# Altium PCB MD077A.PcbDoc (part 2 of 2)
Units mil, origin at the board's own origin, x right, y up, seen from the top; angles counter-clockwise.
Board outline 2838.2 x 1916.85 mil, 4 copper layers (Top Layer, Signal Layer 1, Signal Layer 2, Bottom Layer), stack 61.2 mil thick; 81 components, 30 nets, 187 pads, 201 vias.
Unrouted connection lines stored in the file: 7.
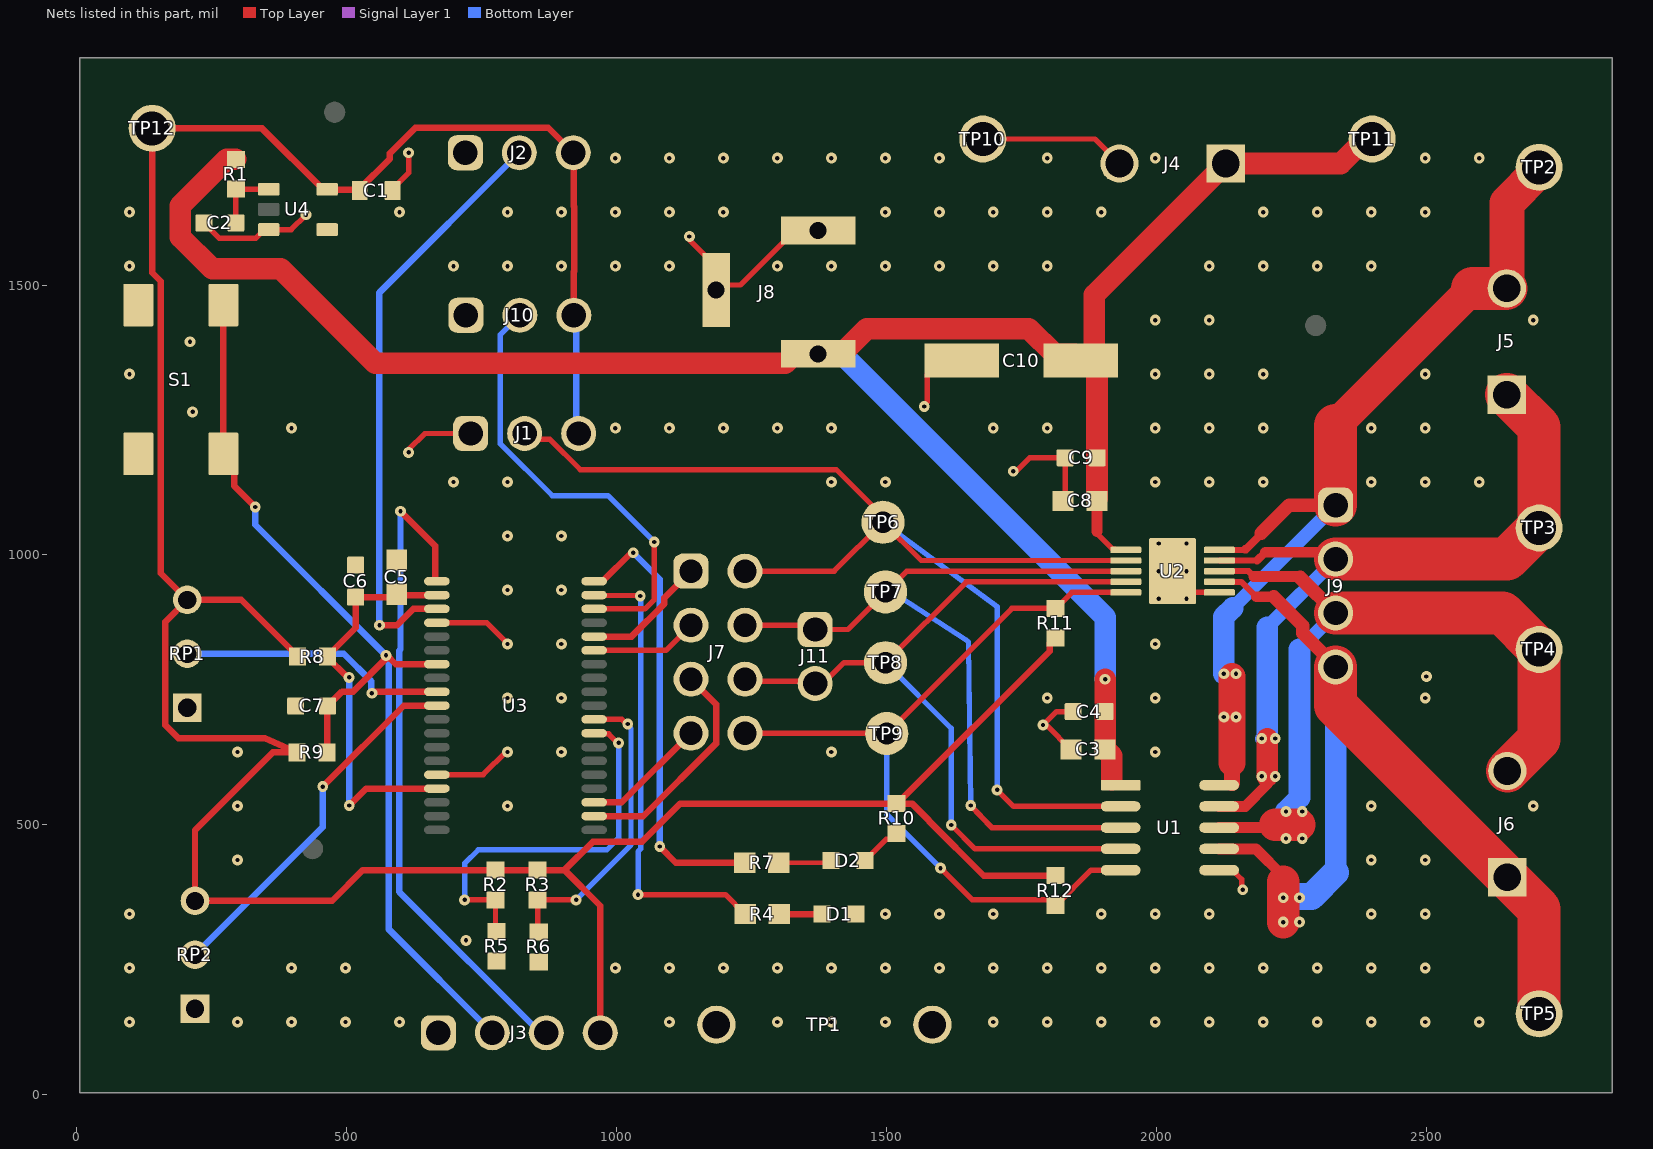
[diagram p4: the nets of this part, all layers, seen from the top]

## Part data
C1: library part CMP-0091702-1, "4.7µF ±10% 25V Ceramic Capacitor X5R 0603 (1608 Metric)", Digikey Part Number=490-14462-1-ND, Manufacturer=Murata, Mouser Part Number=81-GRM188R61E475KE5D, Operating Temperature Range="-55°C to +85°C", TempCo=15%, Temperature Characteristic=X5R, Tolerance_%=10%, ValueDisplayed=4.7uF
C2 C4 C6 C9: library part CMP-0096736-1, "10 µF ±20% 25V Ceramic Capacitor X5R 0603 (1608 Metric)", Manufacturer=Wurth, Operating Temperature Range="-55°C to +85°C", TempCo=15%, Temperature Characteristic=X5R, Tolerance_%=20%, ValueDisplayed=10uF
C3 C5 C8: library part CMP-0006832-5, "CAP, CERM, 0.1 uF, 25 V, +/- 10%, X7R, 0603", Cap_Case=0603, Manufacturer="Wurth Elektronik", Supplier Part Number 1=710-885012206071, TempCo=X7R, Tolerance_%=10%, Value1=Unknown, Value2=25V, ValueDisplayed=0.1uF
C7: library part CMP-0097310-1, "1000 pF ±5% 25V Ceramic Capacitor C0G, NP0 0603 (1608 Metric)", Digikey Part Number=732-7786-1-ND, Manufacturer="Wurth Electronics", Mouser Part Number=710-885012006044, Operating Temperature Range="-55°C to +125°C", TempCo=30ppm/°C, Temperature Characteristic=NP0, Tolerance_%=5%, ValueDisplayed=1nF
C10: library part CMP-0107003-1, "WCAP-ASLI Aluminum Electrolytic Capacitor, V-Chip, D6.3 x H5.5mm, 47uF, 25V", Capacitance Tolerance=+/-20%, Leakage Current=11.75uA, Manufacturer="Wurth Elektronik", Operating Temperature Max=105°C, Operating Temperature Min=-55°C, Rated Voltage (DC)=25V, Ripple Current=220mA
D1: library part CMP-0002894-2, "LED, Green, SMD", Color=green, Manufacturer="Wurth Elektronik", Value1=W, Value2=2V
D2: library part CMP-0002947-3, "LED, Red, SMD", Color=Red, Manufacturer="Wurth Elektronik", Power_TotalModule=72mW, Value1=0.072W, Value2=2V
FID1 FID2 FID3: library part CMP-0077181-1, "Fiducial mark.  There is nothing to buy or mount.", Manufacturer=N/A
H1 H2 H3 H4: library part CMP-0003621-1, "Bumpon, Cylindrical, 0.312 X 0.200, Black", Manufacturer=3M, Supplier Part Number 1=SJ5746-0-ND
J1 J2 J10: library part CMP-0054796-4, "Header, 2.54 mm, 3x1, Gold, TH", Manufacturer="Wurth Elektronik", Supplier Part Number 1=732-5316-ND
J3 J9: library part CMP-0054798-2, "Header, 2.54 mm, 4x1, Gold, TH", Color=Black, Manufacturer="Wurth Elektronik", Supplier Part Number 1=732-5317-ND
J4 J5 J6: library part CMP-0054828-1, "Terminal Block, 5 mm, 2x1, Tin, TH", Manufacturer="Wurth Elektronik", Supplier Part Number 1=732-2026-ND
J7: library part CMP-1502-01078-2, "CONN HEADER VERT 8POS 2.54MM", Color=Black, Contact Resistance=20mΩ, Current Rating=3A, Manufacturer="Wurth Electronics", Max Operating Temperature=105°C, Min Operating Temperature=-40°C, Operating Supply Voltage=250V
J8: library part CMP-0054778-4, "WR-DC DC Power Jack, R/A, TH", Color=Black, Manufacturer="Wurth Elektronik", Supplier Part Number 1=732-5930-ND
J11: library part CMP-0054794-2, "Header, 2.54 mm, 2x1, Gold, TH", Color=Black, Manufacturer="Wurth Elektronik", Supplier Part Number 1=732-5315-ND
LBL1: library part CMP-0003625-1, "Thermal Transfer Printable Labels, 0.650\" W x 0.200\" H - 10,000 per roll", Manufacturer=Brady, Supplier Part Number 1=97C5133
LBL2: library part CMP-00007-1, "Harsh Environment Multi-Purpose Polyester Labels for 3\" Core Printers - 0.375\" x 0.375\", White", Manufacturer=Brady, PartNumber=THT-14-423-10, Supplier Part Number 1=97C5133
Logo1: library part CMP-0074838-1, "Texas Instrument Corporate Signature"
Logo2: library part CMP-0074844-1
Logo3: library part CMP-0074847-1, "FCC_disclaimer"
Logo4: library part CMP-0074769-3, Manufacturer="Texas Instruments"
LOGO5 LOGO6 LOGO7: library part CMP-0074837-2, "IEC 61010-1 Hot Surface Warning", Manufacturer="Texas Instruments"
R1 R8: library part CMP-0025874-4, "RES, 0, 5%, 0.1 W, AEC-Q200 Grade 0, 0603", Manufacturer=Panasonic, Power_W=100mW, Supplier Part Number 1=P0.0GCT-ND, TempCo="600 ppm/C", Tolerance_%=5%, Value2=0.1W, Value_Code=0000, ValueDisplayed=0
R2 R3 R5 R6 R10 R11 R12: library part CMP-0025886-5, "RES, 10 k, 5%, 0.1 W, 0603", Manufacturer=Yageo, Power_W=100mW, Supplier Part Number 1=311-10KGRCT-ND, TempCo="100 ppm/C", Tolerance_%=5%, Value2=0.1W, Value_Code=10k0, ValueDisplayed=10k
R4 R7: library part CMP-0025912-5, "RES, 330, 5%, 0.1 W, 0603", Manufacturer=Yageo, Power_W=100mW, Supplier Part Number 1=311-330GRCT-ND, TempCo="100 ppm/C", Tolerance_%=5%, Value2=0.1W, Value_Code=330R, ValueDisplayed=330
R9: library part CMP-0025814-4, "RES, 47 k, 5%, 0.1 W, AEC-Q200 Grade 0, 0603", Manufacturer=Vishay-Dale, Power_W=100mW, Supplier Part Number 1=541-47KGCT-ND, TempCo="200 ppm/C", Tolerance_%=5%, Value2=0.1W, Value_Code=47k0, ValueDisplayed=47k
RP1 RP2: library part CMP-0001777-2, "Trimming Potentiometer, 50K, 0.5W, TH", Manufacturer=Bourns, Supplier Part Number 1=3352T-503LF-ND
S1: library part CMP-0097347-1, "Tactile Switch SPST-NO Top Actuated Surface Mount", Coil Resistance_ohm=100mΩ, Contact Current Rating=50mA, Digikey Part Number=732-7022-1-ND, Manufacturer="Wurth Electronics", Mouser Part Number=710-430481025816, Operating Force=160gf, Operating Temperature Range="-40°C to +85°C"
SH-J1 SH-J2 SH-J3 SH-J4 SH-J5 SH-J6 SH-J10: library part CMP-0003761-2, "Shunt, 2.54mm, Gold, Black", Manufacturer="Wurth Elektronik", Supplier Part Number 1=732-2678-ND
TP1: library part CMP-0075110-1, "1mm Uninsulated Shorting Plug, 10.16mm spacing, TH", Manufacturer=Harwin, PartNumber=D3082-05, Supplier Part Number 1=952-1873-ND
TP2 TP3 TP4 TP5: library part CMP-0055149-2, "Test Point, Multipurpose, White, TH", Color=White, Manufacturer="Keystone Electronics", Supplier Part Number 1=36-5012-ND
TP6 TP7 TP8 TP9: library part CMP-0055139-2, "Test Point, Miniature, White, TH", Color=White, Manufacturer="Keystone Electronics", Supplier Part Number 1=36-5002-ND
TP10: library part CMP-0055148-2, "Test Point, Multipurpose, Black, TH", Color=Black, Manufacturer="Keystone Electronics", Supplier Part Number 1=36-5011-ND
TP11: library part CMP-0055147-2, "Test Point, Multipurpose, Red, TH", Color=Red, Manufacturer="Keystone Electronics", Supplier Part Number 1=36-5010-ND
TP12: library part CMP-0055150-2, "Test Point, Multipurpose, Orange, TH", Color=Orange, Manufacturer="Keystone Electronics", Supplier Part Number 1=36-5013-ND
U1: library part CMP-0065579-1, "Dual H-Bridge Stepper Driver, SSOP10", Manufacturer="Texas Instruments", Max Supply Voltage=18V, Min Supply Voltage=4V, Nominal Supply Current=3.8mA, Operating Temperature Range="-40°C to +150°C", Switching Frequency=250kHz
U2: library part CMP-0065580-1, "Dual H-Bridge Stepper Driver", Manufacturer="Texas Instruments", Max Supply Voltage=18V, Min Supply Voltage=4V, Nominal Supply Current=3.8mA, Operating Temperature Range="-40°C to +150°C", Switching Frequency=250kHz
U3: library part CMP-0076631-1, "MSP430G2x55 Mixed Signal Microcontroller, DA0038A (TSSOP-38)", Alternate Manufacturer="Texas Instruments", Alternate PartNumber=MSP430G2955IDA38
U4: library part CMP-0077328-2, "40-V Ultralow-Iq Low-Dropout Regulator, DBV0005A (SOT-23-5)", Alternate Manufacturer="Texas Instruments"
ZZ1: library part CMP-0077236-1
ZZ2: library part CMP-0077237-1
ZZ3: library part CMP-0077238-1
ZZ4: library part CMP-0003616-3

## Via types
v1: diameter 20, hole 8, Top Layer to Bottom Layer, tented both sides, 178 vias
v2: diameter 20, hole 8, Top Layer to Bottom Layer, 17 vias
v3: diameter 19.68, hole 7.87, Top Layer to Bottom Layer, tented both sides, 6 vias

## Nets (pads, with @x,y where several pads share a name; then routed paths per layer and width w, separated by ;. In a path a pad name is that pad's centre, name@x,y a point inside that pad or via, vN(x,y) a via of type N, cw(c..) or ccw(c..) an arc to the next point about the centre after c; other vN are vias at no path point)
GND: C1.1 C2.1 C3.2 C4.1 C5.2 C6.1 C7.1 C8.2 C9.1 C10.2 D1.1 J1.1 J2.1 J3.1 J4.2 J8.2 J8.3 J10.1 R5.2 R6.2 RP1.1 RP2.1 S1.3 S1.4 TP1.1 TP1.2 TP10.1 U1.6 U2.6 U2.11 U3.4 U3.15 U4.3 U4.4 | length 1911.6
  Top Layer w10: C2.1@235.94,1615 264.57,1586.38 331.77,1586.38 345.39,1600 U4.3@355,1600 ; U4.3@355.87,1602.6 397.6,1602.6 v1(425,1630) ; C1.1@585.51,1675 585.51,1677.95 615,1707.44 v1(615,1745) ; v1@615,1195 645,1225 J1.1@730,1225 ; U3.15@667.33,593.05 753.05,593.05 v1@797,637 ; U3.4@667.33,874.54 759.46,874.54 v1@797,837 ; v1(1135,1590) 1136.91,1588.09 1136.91,1581.85 1185,1533.76 J8.3@1185,1505 ; J8.3@1190,1500 1229.37,1500 1330.36,1601 J8.2@1373.67,1601 ; v1(1570,1275) 1570,1277.71 1575.87,1283.57 1575.87,1333.5 1602.36,1360 C10.2@1639.76,1360 ; TP10.1@1678.42,1770.38 1886.19,1770.38 1930,1726.57 J4.2@1930,1725 ; v1@1740,1155 1765,1180 C9.1@1830.94,1180 1830.94,1100.94 C8.2@1830,1100 ; C3.2@1842.01,640 1841.02,640 1797.94,683.09 1791.91,683.09 v1(1790,685) 1815,710 C4.1@1845.94,710 ; v3(2055.59,918.82) 2067.4,930.63 U2.6@2116.61,930.63 ; U1.6@2116.18,416.26 2141.04,416.26 2158.09,399.21 2158.09,381.91 v1(2160,380)
  other v1: 98,135 298,135 398,135 498,135 598,135 1098,135 1298,135 1398,135 1498,135 1698,135 1798,135 1898,135 1998,135 2098,135 2198,135 2298,135 2398,135 2498,135 2598,135 98,235 398,235 498,235 998,235 1098,235 1198,235 1298,235 1398,235 1498,235 1598,235 1698,235 1798,235 1898,235 1998,235 2098,235 2198,235 2298,235 2398,235 2498,235 721.27,286.26 98,335 1498,335 1598,335 1698,335 1898,335 1998,335 2098,335 2398,335 2498,335 298,435 2398,435 2498,435 298,535 798,535 2398,535 2698,535 298,635 798,635 898,635 1398,635 1998,635 798,735 898,735 1798,735 1998,735 2498,735 2500,775 798,835 898,835 1998,835 798,935 898,935 798,1035 898,1035 698,1135 798,1135 1398,1135 1498,1135 1998,1135 2098,1135 2198,1135 2398,1135 2498,1135 2598,1135 1735,1155 615,1190 398,1235 998,1235 1098,1235 1198,1235 1298,1235 1398,1235 1698,1235 1798,1235 1998,1235 2098,1235 2198,1235 2398,1235 2498,1235 215,1265 98,1335 1998,1335 2098,1335 2198,1335 2498,1335 210,1395 1998,1435 2098,1435 2698,1435 98,1535 698,1535 798,1535 898,1535 998,1535 1098,1535 1298,1535 1398,1535 1498,1535 1598,1535 1698,1535 1798,1535 2098,1535 2198,1535 2298,1535 2398,1535 98,1635 598,1635 798,1635 898,1635 998,1635 1098,1635 1198,1635 1498,1635 1598,1635 1698,1635 1798,1635 1898,1635 2198,1635 2298,1635 2398,1635 2498,1635 998,1735 1098,1735 1198,1735 1298,1735 1398,1735 1498,1735 1598,1735 1798,1735 1998,1735 2498,1735 2598,1735
  other v3: 2004.41,918.82 2004.41,970 2055.59,970 2004.41,1021.18 2055.59,1021.18
ID1: R2.2 R5.1 U3.27 | length 717.4
  Top Layer w10: v2(718.73,361.27) R2.2@776,361.27 776,304.99 R5.1@778,302.99 ; U3.27@958.67,669.82 959.77,668.72 985.36,668.72 1002.08,652 v2(1004,652)
  Bottom Layer w10: v2(718.73,361.27) 718.73,428.73 744,454 982,454 1004,476 v2(1004,652)
ID2: R3.2 R6.1 U3.28 | length 567.9
  Top Layer w10: R6.1@856,301.56 854,303.56 R3.2@854,361.27 v2(925.27,361.27) ; U3.28@958.67,695.41 1009.88,695.41 1018.29,687 v2(1021,687)
  Bottom Layer w10: v2(925.27,361.27) 1026.87,462.87 1026.87,678.42 1021,684.29 v2(1021,687)
IN1/EN: J1.2 J7.2 TP6.1 U1.2 U2.2 | length 2355.6
  Top Layer w10: J1.2@830,1225 840.52,1214.48 876.38,1214.48 932.99,1157.87 1407.47,1157.87 1493.61,1071.74 TP6.1@1493.61,1060.52 ; J7.2@1238,970 1403.09,970 TP6.1@1493.61,1060.52 ; v1(1705,565) 1735.63,534.37 1934.37,534.37 U1.2@1935,535 ; U2.2@1943.39,989.68 1564.44,989.68 TP6.1@1493.61,1060.52
  Bottom Layer w10: TP6.1@1493.61,1060.52 1705,904.13 v1(1705,565)
IN1/EN_MCU: J7.1 U3.34 | length 235.9
  Top Layer w12: U3.34@958.67,848.95 1027.99,848.95 1088.87,909.83 1088.87,920.87 J7.1@1138,970
IN2/IN1: J7.4 J11.1 TP7.1 U1.3 U2.3 | length 1532
  Top Layer w10: J7.4@1238,870 1360,870 J11.1@1368,862 1428.6,862 TP7.1@1498.29,931.69 1499.46,931.69 1537.77,970 U2.3@1943.39,970 ; v1(1656,536) 1695,495 U1.3@1933.82,495
  Bottom Layer w10: TP7.1@1498.29,931.69 1504.61,933.03 1508.62,933.03 1648.3,842.06 1651.91,838.45 1651.97,834.39 v1@1656,539 ; v1@1655,535 v1(1656,536)
IN2/IN1_MCU: J7.3 U3.33 | length 198.6
  Top Layer w10: U3.33@958.67,823.36 1091.36,823.36 J7.3@1138,870
IN3/IN2: J7.6 J11.2 TP8.1 U1.4 U2.4 | length 1465.4
  Top Layer w10: J7.6@1238,770 1242,766 1364,766 J11.2@1368,762 1382.87,762 1421.4,800.53 TP8.1@1498.29,800.53 1648.08,950.32 U2.4@1943.39,950.32 ; v1(1620,500) 1664.37,455.63 U1.4@1929.37,455.63
  Bottom Layer w10: TP8.1@1498.29,800.53 1620,678.82 v1(1620,500)
IN3/IN2_MCU: J7.5 U3.21 | length 419.8
  Top Layer w12: U3.21@958.67,516.28 1049.83,516.28 1184.35,650.8 1184.35,723.65 J7.5@1138,770
IN4/nFAULT: J7.8 R11.2 R12.2 TP9.1 U1.5 U2.5 | length 1501.9
  Top Layer w10: J7.8@1238,670 1238.32,669.68 1500.32,669.68 TP9.1@1500.64,669.36 1732.4,901.12 R11.2@1813,901.12 1813.98,901.12 1843.5,930.63 U2.5@1943.39,930.63 ; v1@1606.45,416.26 1602.71,420 v1(1600,420) 1658.37,361.63 1802.03,361.63 R12.2@1812.78,350.88 1813.77,350.88 1879.14,416.26 U1.5@1933.82,416.26
  Bottom Layer w10: TP9.1@1500.64,669.36 1500.64,519.36 v1(1600,420)
IN4/nFAULT_MCU: J7.7 U3.22 | length 234.8
  Top Layer w12: U3.22@958.67,541.87 1009.87,541.87 J7.7@1138,670
  Signal Layer 1 w12: J7.7@1149.36,680.06 J7.7@1151.06,681.76
"MCU 3V3": C1.2 J1.3 J2.3 J3.4 J10.3 R2.1 R3.1 R8.2 R9.1 R10.1 R11.1 R12.1 RP1.3 RP2.3 TP12.1 U4.5 | length 5942.5
  Top Layer w12: R8.2@409.44,811.65 409.44,812.63 305.07,917.01 RP1.3@205.01,917.01 ; J10.3@921,1444 921,1524.24 921.87,1525.11 921.87,1644.89 921,1645.76 921,1744 J2.3@920,1745 873.65,1791.35 627.59,1791.35 580.42,1744.18 580.42,1733.89 523.29,1676.75 523.29,1676.2 465.33,1676.2 U4.5@464.13,1677.4 456.26,1677.4 343.66,1790 TP12.1@140,1790 140,1522.78 156,1506.78 156,966.02 RP1.3@205.01,917.01 ; J3.4@970,115 970,350.29 903.91,416.38 ; R12.1@1812.78,406 1680.24,406 1578.78,507.46 1578.78,508.22 1547.44,539.56 R10.1@1519.98,539.56 ; R11.1@1813,846 1812.02,846 1802.27,836.25 1802.27,821.84 R10.1@1519.98,539.56 ; RP1.3@205.01,917.01 164.56,876.56 164.56,684.68 188.37,660.87 348.02,660.87 R9.1@408.44,634.2 363.44,634.2 219.38,490.14 RP2.3@219.38,359.54 473.4,359.54 530.25,416.38 R2.1@776,416.38 R3.1@854,416.38 903.91,416.38 ; 903.91,416.38 956.46,468.94 1047.34,468.94 1117.96,539.56 R10.1@1519,539.56 R10.1@1519.98,539.56
  Bottom Layer w12: J10.3@921,1444 925.5,1439.5 925.5,1229.5 J1.3@930,1225
MCU_STATUS: R4.1 U3.37 | length 854.9
  Top Layer w10: U3.37@958.81,925.86 U3.37@958.67,925.72 959.53,924.86 1043.14,924.86 v2(1044,924) ; v2(1040,371) 1201.52,371 1237.52,335 R4.1@1238.5,335
  Bottom Layer w10: v2(1040,371) 1040,450.72 1044.75,455.47 1044.75,923.25 v2(1044,924)
MODE_SELECT: J2.2 U3.3 | length 1101.1
  Top Layer w12: v2(561,870) 593.5,870 623.64,900.13 U3.3@667.33,900.13
  Bottom Layer w12: v2(561,870) 561,1486 J2.2@820,1745
NetC2_2: C2.2 R1.1 U4.1 | length 120.1
  Top Layer w10: C2.2@295,1615 R1.1@295,1677.44 306.69,1677.44 306.73,1677.4 U4.1@352.6,1677.4
NetC5_1: C5.1 C6.2 R8.1 U3.2 U3.16 | length 756.4
  Top Layer w12: v2(505,536) 536.46,567.46 U3.16@667.33,567.46 ; v2@507,775 500.22,775 464.56,810.66 R8.1@464.56,811.65 464.56,812.63 517,865.07 C6.2@517,922 587.5,922 C5.1@593,927.5 594.78,925.72 U3.2@667.33,925.72
  Bottom Layer w12: v2(504.84,773.36) 504.92,773.28 504.92,536.08 v2(505,536)
NetD1_2: D1.2 R4.2 | length 79.5
  Top Layer w12: R4.2@1301.5,335 D1.2@1381.01,335
NetD2_1: D2.1 R7.2 | length 99.7
  Top Layer w8: R7.2@1300.5,430 1393.01,430 D2.1@1397.01,434 D2.1@1398.5,434
NetD2_2: D2.2 R10.2 | length 79.9
  Top Layer w10: D2.2@1460,434 1499.69,473.69 1508.25,473.69 R10.2@1519,484.44
nFAULT_STATUS: R7.1 U3.38 | length 828.4
  Top Layer w12: U3.38@958.67,951.32 959.89,952.54 975.64,952.54 1025.57,1002.47 1029.47,1002.47 v2(1031,1004) ; v2(1080,460) 1110,430 R7.1@1237.5,430
  Bottom Layer w12: v2(1031,1004) 1080,955 v2(1080,460)
OUT1: J5.2 J9.1 TP2.1 U1.10 U2.10 | length 1687.5
  Top Layer w10: U1.10@2116.18,573.74 2135.78,573.74 U1.10@2140,577.96
  Top Layer w11: U2.10@2116.61,1009.37 2163.06,1009.37 2164.37,1010.68
  Top Layer w15: 2164.37,1010.68 2165.68,1010.68 2195,1040
  Top Layer w25: 2194.34,1040.66 2246.19,1092.5 J9.1@2331.9,1092.5
  Top Layer w30: U1.10@2140,577.96 2140,615
  Top Layer w50: 2140,615 v1@2140,775
  Top Layer w60: 2331.9,1239.93 2585.79,1493.81
  Top Layer w65: J5.2@2649.02,1493.81 2649.02,1652.23 2708.69,1711.9 TP2.1@2708.69,1717.85
  Top Layer w80: J9.1@2331.9,1092.5 2331.9,1239.93 ; 2585.79,1493.81 J5.2@2647.11,1493.81
  Bottom Layer w25: 2141.18,901.79 J9.1@2331.9,1092.5
  Bottom Layer w40: v1(2125,780) 2125,885.6 2141.18,901.79
  other v1: 2125,700 2147.5,700 2147.5,780
OUT2: J5.1 J9.2 TP3.1 U1.9 U2.9 | length 1442.2
  Top Layer w11: U2.9@2116.61,989.68 2186.62,989.68
  Top Layer w15: 2186.62,989.68 2201.93,1005
  Top Layer w20: U1.9@2116.18,534.37 2164.37,534.37 2205.25,575.25 ; 2201.93,1005 J9.2@2315,1005
  Top Layer w40: 2205,590 2205,660
  Top Layer w80: J9.2@2331.9,992.5 2649.3,992.5 2706.8,1050 TP3.1@2708.69,1050 2708.69,1237.29 J5.1@2649.02,1296.96
  Bottom Layer w25: v1(2195,660) 2205,670 ; 2205,865.6 J9.2@2331.9,992.5
  Bottom Layer w40: 2205,670 2205,865.6
  other v1: 2195,590 2220,590 2220,660
OUT3: J6.2 J9.3 TP4.1 U1.8 U2.8 | length 1460.6
  Top Layer w10: 2170,970 2170.71,970
  Top Layer w11: U2.8@2116.61,970 2170,970
  Top Layer w12: 2170.71,970 2180.35,960.35
  Top Layer w20: U1.8@2116.18,495 2215,495 ; 2180.35,960.35 2264.65,960.35 2265,960
  Top Layer w25: 2266.07,958.33 J9.3@2331.9,892.5 ; TP4.1@2708.69,810.26 TP4.1@2708.69,824.98
  Top Layer w60: 2220,500 2265,500
  Top Layer w80: J9.3@2331.9,892.5 2641.17,892.5 TP4.1@2708.69,824.98 ; J6.2@2650,600 2708.69,658.69 TP4.1@2708.69,821.75
  Bottom Layer w25: 2265,825.6 J9.3@2331.9,892.5
  Bottom Layer w40: v1(2240,525) 2265,550 2265,825.6
  other v1: 2240,475 2270,475 2270,525
OUT4: J6.1 J9.4 TP5.1 U1.7 U2.7 | length 1796.5
  Top Layer w11: U2.7@2116.61,950.32 2157.34,950.32 2185.15,922.5
  Top Layer w20: U1.7@2116.18,455.63 2184.37,455.63 2235,405 ; 2185.15,922.5 2217.5,922.5
  Top Layer w25: 2217.5,922.5 2270.88,869.12 2270.88,854.95 2331.9,793.93 J9.4@2331.9,792.5
  Top Layer w60: v1(2235,320) v1(2235,365) 2235,395
  Top Layer w80: J9.4@2331.9,792.5 2331.9,721.25 2708.69,344.46 TP5.1@2708.69,150
  Bottom Layer w40: 2331.9,411.9 J9.4@2331.9,792.5
  Bottom Layer w50: v1@2237.5,367.5 2287.5,367.5 2331.9,411.9
  other v1: 2265,320 2265,365
RST/SBWTDIO: C7.2 J3.2 R9.2 S1.1 S1.2 U3.7 | length 1895.4
  Top Layer w12: S1.2@272.05,1177.95 S1.2@275,1175 ; S1.1@272.05,1462.8 S1.2@272.05,1187.2 291.68,1167.57 291.68,1128.32 v2(331,1089) ; R9.2@463.56,634.2 464.28,634.92 C7.2@464.28,719.6 ; C7.2@465,720.32 491.72,747.03 512.27,747.03 571.47,806.23 571.47,812.47 v2(573,814) 575.16,814 591.39,797.77 U3.7@667.33,797.77
  Bottom Layer w12: v2(331,1089) 331,1056 v2(573,814) 577.88,809.12 577.88,307.12 J3.2@770,115
SBWTCK: J3.3 U3.1 | length 1244.6
  Top Layer w12: v2(600,1081) 664.31,1016.69 664.31,953.05 665.6,953.05 U3.1@667.33,951.32
  Bottom Layer w12: v2(600,1081) 600,825.25 597.76,823.01 597.76,376.01 858.77,115 J3.3@870,115
"SPD_REF 1": RP1.2 U3.9 | length 505.9
  Top Layer w12: v2(547,744) 549.16,744 551.76,746.59 U3.9@667.33,746.59
  Bottom Layer w12: RP1.2@205.01,817.01 494.95,817.01 545.47,766.49 545.47,745.53 v2(547,744)
"SPD_REF 2": RP2.2 U3.10 | length 682.9
  Top Layer w12: v2(456,571) 606,721 U3.10@667.33,721
  Bottom Layer w12: RP2.2@219.38,259.54 456,496.16 v2(456,571)
STEP_SELECT: J10.2 U3.36 | length 838.6
  Top Layer w10: U3.36@958.67,900.13 1052.48,900.13 1070,917.65 v2(1070,1024)
  Bottom Layer w10: J10.2@821,1444 784.65,1407.65 784.65,1206.21 881.02,1109.84 984.16,1109.84 v2(1070,1024)
VM: C3.1 C4.2 C8.1 C9.2 C10.1 J4.1 J8.1 R1.2 TP11.1 U1.1 U2.1 | length 4141.2
  Top Layer w6: U2.1@1923.94,1009.37 U2.1@1943.39,1009.37
  Top Layer w10: 1890,1043.31 1890,1040.12 1919.84,1010.28 1923.03,1010.28 U2.1@1923.94,1009.37
  Top Layer w20: 1890,1043.31 C8.1@1890,1100
  Top Layer w40: R1.2@295,1732.56 278.22,1732.56 192.32,1646.66 192.32,1588.91 251.19,1530.04 377.85,1530.04 552.89,1355 1312.71,1355 1330.36,1372.65 J8.1@1373.67,1372.65 ; J8.1@1380,1375 1383.24,1378.24 1422.57,1378.24 1463.7,1419.37 1763.46,1419.37 1811.34,1371.5 1848.74,1371.5 C10.1@1860.24,1360 ; C10.1@1885,1373.79 1885,1481.57 J4.1@2128.43,1725 ; C8.1@1890,1105 C10.1@1890,1336 ; v1(1905,770) C4.2@1905,710 C3.1@1905,640 1916.93,628.07 1916.93,584.18 ; J4.1@2130,1725 2341.59,1725 2386.97,1770.38 TP11.1@2399.69,1770.38
  Bottom Layer w15: J8.1@1373.67,1372.65 J8.1@1416.98,1372.65
  Bottom Layer w40: J8.1@1416.98,1372.65 1905,884.63 v1(1905,770)
pads on no net: FID1.1 FID2.1 FID3.1 H1.0 H2.0 H3.0 H4.0 LBL1.0 LBL2.0 SH-J1.0 SH-J2.0 SH-J3.0 SH-J4.0 SH-J5.0 SH-J6.0 SH-J10.0 U3.5 U3.6 U3.8 U3.11 U3.12 U3.13 U3.14 U3.17 U3.18 U3.19 U3.20 U3.23 U3.24 U3.25 U3.26 U3.29 U3.30 U3.31 U3.32 U3.35 U4.2

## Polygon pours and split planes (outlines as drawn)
GND on Signal Layer 1 "SIGNAL_LAYER_1_GND_P184" (solid, pour order 184): 28.76,3239.13 4589.98,3239.13 4589.98,2.13 20.98,2.13
GND on Signal Layer 2 "SIGNAL_LAYER_2_GND_P275" (solid, pour order 275): 20.98,2.13 4589.98,2.13 4589.98,3241.13 20.98,3241.13
GND on Bottom Layer "BOTTOM_LAYER_GND_P277" (solid, remove dead copper, pour order 277): 4589.33,3329.38 34.92,3329.38 34.92,106.47 4589.33,106.47
GND on Top Layer "TOP_LAYER_GND_P278" (solid, remove dead copper, pour order 278): -689.89,-781.89 5340.11,-781.89 5340.11,3389.11 -689.89,3389.11

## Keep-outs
Keep-Out Layer:
  text ".Layer_Name" at 575,-2292.49 h25

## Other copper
Top Layer:
  rectangle net OUT4: 2215,300 2285,385
  rectangle net OUT3: 2225,459.54 2285.03,550
  rectangle net OUT2: 2180,575 2235,680
  rectangle net OUT1: 2105,685 2165,795
  text ".Layer_Name" at 575,-2292.49 h25
Bottom Layer:
  text ".Layer_Name" at 575,-2292.49 h25

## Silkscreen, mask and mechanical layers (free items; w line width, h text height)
Top Overlay:
  circle w15: c659.71,1002.62 r7.07
  lines w10: 649.28,1512.1 1105,1512.1 ; 645,1285 1105,1285 ; 645,1285 645,1110 1105,1110 1105,1285 ; 645,1285 1105,1285 ; 645,1285 645,1875 1105,1875 1105,1285 ; 425,40 1110,40 1110,180 425,180 425,40 ; 1773,317 2219,317 2219,764 1773,764 1773,317 ; 1786,827 2212,827 2212,1214 1786,1214 1786,827
  text "VM" at 1118,1848 h40
  text "OUT1" at 2648,1813 h40
  text "Mode Select" at 655,1811.02 h85
  text "4-18V / 4A" at 2470,1785 h35
  text "3.3 V" at 65,1675 h30
  text "Stepper" at 899.56,1670.25 h35 r315
  text "BDC" at 692.31,1660 h40 r315
  text "GND" at 1628,1643 h40
  text "VM" at 2368,1643 h40
  text "(DRV8421A / ONLY)" at 353.73,1316 h55
  text "Half / Step" at 664.52,1283 h30
  text "Full / Step" at 886,1283 h30
  text "OUT2" at 2648,1138 h40
  text "Enable" at 881,1131 h30
  text "Sleep" at 661,1126 h30
  text "(DRV8421B / ONLY)" at 354.85,1120 h55
  text "Reset" at 131,1100 h30
  text "OUT1" at 2388,1073 h40
  text "IN1/EN" at 1561,1045 h33
  text "OUT2" at 2388,968 h40
  text "MCU Ctrl 1" at 324,948 h35 r270
  text "IN2/IN1" at 1566,913 h33
  text "OUT3" at 2648,913 h40
  text "OUT3" at 2383,868 h40
  text "DRV8421 DGQ" at 1850,843 h33
  text "IN3/IN2" at 1566,786 h33
  text "OUT4" at 2388,778 h40
  text "IN4/" at 1578,682 h33
  text "nFAULT" at 1573,624 h33
  text "MD077A" at 1086.75,553.19 h40
  text "nFAULT" at 1314,488 h30
  text "MCU Ctrl 2" at 332,401 h35 r270
  text "DRV8421 DFU" at 1852,343 h33
  text "OUT4" at 2648,243 h40
  text "GND" at 626.95,184.54 h45
  text "3.3V" at 932.4,184.54 h45
  text "MCU  / Status" at 1346,183 h33
  text "EZ FET" at 435,50 h60
  text "GND" at 1303,48 h40
  text ".Layer_Name" at 575,-2292.49 h25
Bottom Overlay:
  lines w10: 1620.13,712 2218.13,712 ; 1621,789 2219,789 ; 1622,974 2220,974 ; 1623,861 2221,861 ; 1623,914 2221,914 ; 1623,1037.68 2221,1037.68 ; 1851.02,632 1853,1035.1 ; 2071.02,632 2073,1035.1 ; 1623,632 2221,632 2221,1095 1623,1095 1623,632
  text "3.3V" at 382,1779 h45
  text "GND" at 1862,1739 h45
  text "VM" at 2308,1734 h45
  text "OUT1" at 2747,1590 h45
  text "GND" at 1417,1529 h35
  text "GND" at 1220.29,1448.19 h35 r270
  text "VM" at 1404,1422 h35
  text "OUT2" at 2762,1153 h45
  text "Inputs" at 1914,1054.01 h25
  text "Pins" at 2191,992 h25
  text "DRV8421B" at 1834,991 h25
  text "DRV8421A" at 2055,989 h25
  text "VM" at 1760.45,922 h25
  text "VM" at 1985.81,922 h25
  text "1" at 2150.09,922 h25
  text "EN" at 1759.59,869 h25
  text "IN1" at 1986.67,869 h25
  text "2" at 2155.26,869 h25
  text "IN1" at 1764.75,797 h25
  text "IN2" at 1987.53,797 h25
  text "3" at 2153.53,797 h25
  text "IN2" at 1771.63,720 h25
  text "IN3" at 1986.67,720 h25
  text "4" at 2156.98,720 h25
  text "OUT3" at 2762,684 h45
  text "nFAULT" at 1809.47,640 h25
  text "IN4" at 1982.36,640 h25
  text "5" at 2154.39,640 h25
  text "OUT4" at 2762,259 h45
  text "SBWTCK" at 853,182 h30 r270
  text "3.3V" at 959,173 h30 r270
  text "GND" at 659,171 h30 r270
  text "RST/SBWTDIO" at 754,171 h30 r270
  text ".Layer_Name" at 575,-2292.49 h25
Top Paste:
  text ".Layer_Name" at 575,-2292.49 h25
Bottom Paste:
  text ".Layer_Name" at 575,-2292.49 h25
Top Solder:
  text ".Layer_Name" at 575,-2292.49 h25
  text ".Layer_Name" at 575,-2292.49 h25
Bottom Solder:
  text ".Layer_Name" at 575,-2292.49 h25
Drill Guide:
  text ".Layer_Name" at 575,-2292.49 h25
M1 Board Outline:
  the board outline again, w10
  text ".Layer_Name" at 575,-2292.49 h25
M2 Board Dimensions:
  rectangle: -2,-1709 123,-1584
  rectangle: 123,-1834 498,-1709
  lines w7: -2,-1709 998,-1709 ; 123,-1834 123,-1584 ; 248,-1834 248,-1584 ; 498,-1834 498,-1584 ; 748,-1834 748,-1584 ; -2,-1834 998,-1834 998,-1584 -2,-1584 -2,-1834
  text ".Layer_Name" at 575,-2292.49 h25
M3 3D STEP Top:
  text ".Layer_Name" at 575,-2292.49 h25
M4 3D STEP Bottom:
  text ".Layer_Name" at 575,-2292.49 h25
M5 Assembly Top:
  lines w10: -294,-2364.17 6306,-2364.17 ; -294,-2160.83 6308,-2160.83 ; -294,-1957.5 -294,-2567.5 3711,-2567.5 6308,-2567.5 6308,-1957.5 -293.5,-1957.5 -293.5,-2567.5 1282,-2567.5 ; 2171,-2567.5 2171,-1957.5 ; 3438,-2160.83 3438,-1957.5 ; 4278,-2160.83 4278,-1957.5 ; 4900,-2574 4900,-2371.17
  text "COMPONENTS MARKED 'DNP' SHOULD NOT BE POPULATED." at 1151.5,-1752.5 h25
  text "ASSEMBLY VARIANT:" at 1151,-1868 h25
  text ".VariantName" at 2187,-1868 h25
  text "PCB VIEWED FROM TOP SIDE" at -230.5,-2089.67 h25
  text "BOARD #:" at 2246,-2089.67 h25
  text ".PRJ_Number" at 2791.5,-2089.67 h25
  text "REV:" at 3636,-2089.67 h25
  text ".PCB_Rev" at 3927.5,-2089.67 h25
  text "SVN REV:" at 4474,-2089.67 h25
  text ".VersionControl_RevNumber" at 4980,-2089.67 h25
  text "TID #:" at 2246,-2293 h25
  text ".TID" at 2791.5,-2293 h25
  text "PLOT NAME =" at -230.5,-2498.34 h25
  text ".plot_File_Name" at 575,-2498.34 h25
  text "GENERATED    :" at 2248,-2498.34 h25
  text ".Print_Date" at 3117.5,-2498.34 h25
  text ".Print_Time" at 3846.5,-2498.34 h25
  text "TEXAS INSTRUMENTS" at 5111,-2498.34 h25
M6 Assembly Bottom:
  lines w10: -294.5,-2161.33 6307.5,-2161.33 ; -292.5,-2364.67 6307.5,-2364.67 ; 1113.5,-2574.5 1113.5,-2371.67 ; 1735.5,-2161.33 1735.5,-1958 ; 2575.5,-2161.33 2575.5,-1958 ; 3842.5,-2568 3842.5,-1958 ; 4731.5,-2568 6307,-2568 6307,-1958 -294.5,-1958 -294.5,-2568 2302.5,-2568 6307.5,-2568 6307.5,-1958
  text "COMPONENTS MARKED 'DNP' SHOULD NOT BE POPULATED." at 6100,-1752 h25
  text ".VariantName" at 5056,-1868 h25
  text "ASSEMBLY VARIANT:" at 6095,-1868 h25
  text ".VersionControl_RevNumber" at 1033.5,-2090.17 h25
  text "SVN REV:" at 1539.5,-2090.17 h25
  text ".PCB_Rev" at 2086,-2090.17 h25
  text "REV:" at 2377.5,-2090.17 h25
  text ".PRJ_Number" at 3222,-2090.17 h25
  text "BOARD #:" at 3767.5,-2090.17 h25
  text "PCB VIEWED FROM BOTTOM SIDE" at 6244,-2090.17 h25
  text ".TID" at 3222,-2293.5 h25
  text "TID #:" at 3767.5,-2293.5 h25
  text "TEXAS INSTRUMENTS" at 902.5,-2498.84 h25
  text ".Print_Time" at 2167,-2498.84 h25
  text ".Print_Date" at 2896,-2498.84 h25
  text "GENERATED    :" at 3765.5,-2498.84 h25
  text ".plot_File_Name" at 5438.5,-2498.84 h25
  text "PLOT NAME =" at 6244,-2498.84 h25
M9 Title Sheet:
  drawing of 57 lines, arcs and shapes, not listed
  text "1" at 737.84,6602.5 h25
  text "2" at 3233.5,6602.5 h25
  text "3" at 5722.84,6602.5 h25
  text "4" at 8229.51,6602.5 h25
  text "5" at 10728.5,6602.5 h25
  text "6" at 13233.5,6602.5 h25
  text "A" at -418.5,5459.5 h25
  text "A" at 14381.5,5459.5 h25
  text "B" at -418.5,3079.5 h25
  text "B" at 14381.5,3079.5 h25
  text "C" at -418.5,704.5 h25
  text "C" at 14381.5,704.5 h25
  text "PROJECT TITLE:" at 11341.5,-1156.5 h25
  text ".PRJ_Title" at 11391.5,-1289.83 h25
  text "DESIGNED FOR:" at 11341.5,-1457.5 h25
  text ".PRJ_Customer" at 11391.5,-1597.5 h25
  text "D" at -418.5,-1665.5 h25
  text "D" at 14381.5,-1665.5 h25
  text "FILE NAME:" at 11341.5,-1757.5 h25
  text ".PCB_File_Name_No_Path" at 11391.5,-1877.5 h25
  text "Texas Instruments (TI) and/or its licensors do not warrant the accuracy or completeness of this specification" at 6372,-2039.34 h25
  text "ENGINEER:" at 11341.5,-2047.5 h25
  text "LAYOUT BY:" at 12846.5,-2047.5 h25
  text "or any information contained therein. TI and/or its licensors do not warrant that this design will meet" at 6327.01,-2152 h25
  text ".PRJ_Engineer" at 11391.5,-2202.49 h25
  text ".PCB_Layout" at 12897,-2202.49 h25
  text "the specifications, will be suitable for your application or fit for any particular purpose, or will operate in" at 6327.01,-2264.67 h25
  text ".Layer_Name" at 575,-2292.49 h25
  text "ALTIUM DESIGNER VERSION:" at 12846.5,-2357.5 h25
  text "an implementation. TI and/or its licensors do not warrant that the design is production worthy. You should" at 6327.01,-2377.33 h25
  text "completely validate and test your design implementation to confirm the system functionality for your application." at 6372,-2490 h25
  text ".print_Scale" at 11391.5,-2490.83 h25
  text ".Application_BuildNumber" at 12897,-2490.83 h25
  text "1" at 737.84,-2697.5 h25
  text "2" at 3233.5,-2697.5 h25
  text "3" at 5722.84,-2697.5 h25
  text "4" at 8229.51,-2697.5 h25
  text "5" at 10728.5,-2697.5 h25
  text "6" at 13233.5,-2697.5 h25
M10 Fab Notes:
  drawing of 189 lines, arcs and shapes, not listed
  text "DESIGN INFORMATION" at 12380.02,4922.17 h25
  text "MIN. TRACK WIDTH:" at 11735.46,4790.05 h25
  text "8" at 12831.7,4790.05 h25
  text "MIL" at 12986.46,4790.05 h25
  text "MIN. CLEARANCE:" at 11735.46,4665.92 h25
  text "0.2" at 12771.7,4665.93 h25
  text "mm" at 12986.46,4665.92 h25
  text "MIN. VIA PAD SIZE:" at 11735.46,4541.8 h25
  text "24" at 12801.71,4541.8 h25
  text "MIL" at 12986.46,4541.8 h25
  text "0.05mm (2MIL)" at 12430.46,4411.9 h25
  text "MINIMUM ANNULAR RING" at 11406.23,4403.67 h25
  text "EXTERNAL" at 13138.46,4403.67 h25
  text "PER" at 11606.23,4293.55 h25
  text "IPC-D-275 CLASS 2 LEVEL C" at 11826.23,4293.54 h25
  text "MIL, HOLES" at 13314.46,4193.07 h25
  text "+/-" at 12922,4184.48 h25
  text "+/-" at 13776,4184.48 h25
  text "REGISTRATION TOLERANCES:" at 11406.23,4183.42 h25
  text "METAL" at 12606,4183.42 h25
  text "5" at 13182.2,4183.42 h25
  text "3" at 14015.2,4183.42 h25
  text "MIL" at 14131.46,4183.42 h25
  text "HOLE SIZE TOLERANCE (UNLESS OTHERWISE SPECIFIED):" at 11406.23,4085.1 h25
  text "+/-" at 13776,4082.23 h25
  text "3" at 14015.2,4081.17 h25
  text "MIL" at 14131.46,4081.17 h25
  text "MATERIAL:" at 11331.46,3943.52 h25
  text "FR-4 High Tg" at 12317.9,3815 h25
  text "X" at 12173.46,3807.01 h25
  text "FR-408" at 11752.46,3802.49 h25
  text "OTHER" at 13240.46,3802.49 h25
  text "62 MIL (1.6mm) +/-10%" at 12072.56,3659.46 h25
  text "X" at 11952.46,3657.01 h25
  text "THICKNESS:" at 11406.23,3651.24 h25
  text "OTHER" at 13357.46,3651.24 h25
  text "TOLERANCE:" at 11406.23,3512.92 h25
  text "X" at 12254.46,3512.92 h25
  text "ANSI IPC-6012 TYPE 3 CLASS 2" at 12432.48,3512.92 h25
  text "OTHER +/-" at 12432.46,3368.73 h25
  text "BOW & TWIST:" at 11406.23,3223.54 h25
  text "X" at 12254.46,3223.54 h25
  text "ANSI IPC-6012 TYPE 3 CLASS 2" at 12432.48,3223.54 h25
  text "OTHER +/-" at 12432.46,3076.85 h25
  text "DRILLING:" at 11331.46,2946.23 h25
  text "NC_DRILL FILES" at 13092.46,2841.04 h25
  text "REFERENCE:" at 11406.23,2837.1 h25
  text "X" at 12063.46,2837.01 h25
  text "AS SHOWN" at 12241.46,2837.1 h25
  text "X" at 12964.46,2837.1 h25
  text "OTHER" at 13390.46,2694.85 h25
  text "PTH COPPER THICKNESS:" at 11405.91,2691.32 h25
  text "X" at 12545.14,2691.32 h25
  text "20-30 um" at 12673.14,2691.32 h25
  text "BOARD FINISH:" at 11331.46,2543.73 h25
  text "SILKSCREEN:" at 11486.68,2433.6 h25
  text "X" at 12444.46,2433.6 h25
  text "TOP" at 12561.46,2433.6 h25
  text "X" at 12954.46,2433.6 h25
  text "BOTTOM" at 13072.46,2433.6 h25
  text "SILKSCREEN COLOR:" at 11486.68,2278.41 h25
  text "X" at 12443.46,2278.41 h25
  text "WHITE" at 12561.46,2278.41 h25
  text "OTHER" at 13072.46,2278.41 h25
  text "X" at 12574.46,2134.96 h25
  text "GREEN" at 12692.46,2134.96 h25
  text "OTHER" at 13310.46,2134.96 h25
  text "SOLDER RESIST COLOR:" at 11486.68,2128.1 h25
  text "X" at 12574.46,1980.71 h25
  text "MATTE" at 12692.46,1980.71 h25
  text "SEMI-GLOSS" at 13310,1980.07 h25
  text "IMMERSION GOLD (ENIG)" at 12392.46,1807.94 h25
  text "ENEPIG" at 13730,1800.72 h25
  text "SURFACE FINISH:" at 11331.46,1799.72 h25
  text "X" at 12214.46,1799.72 h25
  text "IMM. TIN/SILVER OR EQUIV" at 11661,1662.4 h25
  text "OTHER" at 13092.46,1658.47 h25
  text "ARRAY/PANEL:" at 11331.46,1503.09 h25
  text "CUT AND TRIM PER M1 BOARD OUTLINE" at 12392.46,1494.87 h25
  text "N.C. ROUTE" at 12392.46,1358.9 h25
  text "X" at 13080.46,1358.9 h25
  text "V. SCORE" at 13258.46,1358.9 h25
  text "CERTIFICATION:" at 11331.46,1229.77 h25
  text "MATERIALS AND WORKMANSHIP FOR ALL PCBS" at 12056.46,1229.77 h25
  text "TO MEET OR EXCEED THE REQUIREMENTS OF:" at 12056.46,1135.71 h25
  text "X" at 11693.97,1007.08 h25
  text "ANSI IPC-A-600F CLASS ->" at 11821.96,1007.08 h25
  text "X" at 13469.97,1007.08 h25
  text "2" at 13579.96,1007.08 h25
  text "1" at 13264.96,1005.58 h25
  text "3" at 13933.96,1005.58 h25
  text "X" at 12505.97,859.39 h25
  text "RoHS" at 12633.96,859.39 h25
  text "OTHER" at 13278.36,859.39 h25
  text "PER ORDER" at 13675.42,859.39 h25
  text "ALL BOARDS MUST MEET OR EXCEED UL94-V0 REQUIREMENTS." at 11359,705.57 h25
  text "PCB MUST BEAR THE UL94V-0 UL REGISTERED MATERIAL ID NUMBER" at 11359,589.5 h25
  text "ADDITIONAL REQUIREMENTS:" at 11331.46,420.08 h25
  text "MICROSECTION:" at 11406.23,312.95 h25
  text "YES" at 12311.96,312.95 h25
  text "REQUIRED" at 13173.46,168.62 h25
  text "BARE BOARD ELEC. TEST:" at 11406.23,165.76 h25
  text "NONE" at 12711.96,165.76 h25
  text "X" at 13055.46,165.76 h25
  text "PER ORDER" at 13765.46,165.76 h25
  text "XX MIL VIAS REQUIRE NON-CONDUCTIVE FILL AND PLANARIZE" at 11574.38,-39.18 h25
  text "XX MIL VIAS REQUIRE CONDUCTIVE FILL AND PLANARIZE" at 11582.38,-143.16 h25
  text "OUTER XX MIL TRACES REQUIRE 50 OHM SINGLE-ENDED IMPEDANCE" at 11581.39,-306.54 h25
  text "LAYER 2 & 3 (INNER LAYERS) XX MIL WIDE, XX MIL SPACE / TRACES REQUIRE 100 OHM DIFFERENTIAL IMPEDANCE" at 11573.39,-542.26 h25
  text ".Layer_Name" at 575,-2292.49 h25
M11 Gerber Information:
  lines w10: -294,-2364.17 6306,-2364.17 ; -294,-2160.83 6308,-2160.83 ; -294,-1957.5 -294,-2567.5 3711,-2567.5 6308,-2567.5 6308,-1957.5 -293.5,-1957.5 -293.5,-2567.5 1282,-2567.5 ; 2171,-2567.5 2171,-1957.5 ; 3438,-2160.83 3438,-1957.5 ; 4278,-2160.83 4278,-1957.5 ; 4900,-2574 4900,-2371.17
  text "ALL ARTWORK VIEWED FROM TOP SIDE" at -230.5,-2089.67 h25
  text "BOARD #:" at 2246,-2089.67 h25
  text ".PRJ_Number" at 2791.5,-2089.67 h25
  text "REV:" at 3636,-2089.67 h25
  text ".PCB_Rev" at 3927.5,-2089.67 h25
  text "SVN REV:" at 4474,-2089.67 h25
  text ".VersionControl_RevNumber" at 4980,-2089.67 h25
  text "LAYER NAME =" at -230.5,-2292.49 h25
  text "TID #:" at 2246,-2293 h25
  text ".TID" at 2791.5,-2293 h25
  text "PLOT NAME =" at -230.5,-2498.34 h25
  text ".plot_File_Name" at 575,-2498.34 h25
  text "GENERATED    :" at 2248,-2498.34 h25
  text ".Print_Date" at 3117.5,-2498.34 h25
  text ".Print_Time" at 3846.5,-2498.34 h25
  text "TEXAS INSTRUMENTS" at 5111,-2498.34 h25
M12 Stackup:
  drawing of 306 lines, arcs and shapes, not listed
  text "Layer" at 9739.35,6472.5 h25
  text "Name" at 9921.81,6472.5 h25
  text "Material" at 10325.03,6472.5 h25
  text "Thickness" at 10694.94,6472.5 h25
  text "Constant" at 10977.37,6472.5 h25
  text "Board Layer Stack" at 11226.48,6472.5 h25
  text "Top Overlay" at 9921.81,6422.5 h25
  text "Top Solder" at 9921.81,6372.5 h25
  text "Solder Resist" at 10325.03,6372.5 h25
  text "0.40mil" at 10694.94,6372.5 h25
  text "3.5" at 10977.37,6372.5 h25
  text "1" at 9739.35,6322.5 h25
  text "Top Layer" at 9921.81,6322.5 h25
  text "2.80mil" at 10694.94,6322.5 h25
  text "Dielectric 1" at 9921.81,6272.5 h25
  text "FR4 370" at 10325.03,6272.5 h25
  text "11.40mil" at 10694.94,6272.5 h25
  text "4.2" at 10977.37,6272.5 h25
  text "2" at 9739.35,6222.5 h25
  text "Signal Layer 1" at 9921.81,6222.5 h25
  text "1.40mil" at 10694.94,6222.5 h25
  text "Dielectric 2" at 9921.81,6172.5 h25
  text "FR4 370" at 10325.03,6172.5 h25
  text "30.00mil" at 10694.94,6172.5 h25
  text "4.2" at 10977.37,6172.5 h25
  text "3" at 9739.35,6122.5 h25
  text "Signal Layer 2" at 9921.81,6122.5 h25
  text "1.40mil" at 10694.94,6122.5 h25
  text "Dielectric 3" at 9921.81,6072.5 h25
  text "FR4 370" at 10325.03,6072.5 h25
  text "11.40mil" at 10694.94,6072.5 h25
  text "4.2" at 10977.37,6072.5 h25
  text "4" at 9739.35,6022.5 h25
  text "Bottom Layer" at 9921.81,6022.5 h25
  text "2.80mil" at 10694.94,6022.5 h25
  text "Bottom Solder" at 9921.81,5972.5 h25
  text "Solder Resist" at 10325.03,5972.5 h25
  text "0.40mil" at 10694.94,5972.5 h25
  text "3.5" at 10977.37,5972.5 h25
  text "Bottom Overlay" at 9921.81,5922.5 h25
  text ".Layer_Name" at 575,-2292.49 h25
M13 Component Bodies Top:
  text ".Layer_Name" at 575,-2292.49 h25
M14 Component Bodies Bottom:
  text ".Layer_Name" at 575,-2292.49 h25
M15 Courtyards Top:
  text ".Layer_Name" at 575,-2292.49 h25
M16 Courtyards Bottom:
  text ".Layer_Name" at 575,-2292.49 h25
Drill Drawing:
  circle w10: c74.03,6086.88 r11.5
  lines w10: 62.53,6029.39 68.28,6029.39 68.28,6023.64 79.78,6023.64 79.78,6029.39 85.53,6029.39 85.53,6040.89 79.78,6040.89 79.78,6046.64 68.28,6046.64 68.28,6040.89 62.53,6040.89 62.53,6029.39 ; 62.53,6127.13 85.53,6127.13 85.53,6150.12 62.53,6150.12 62.53,6127.13 ; 62.53,6201.87 85.53,6201.87 74.03,6178.87 62.53,6201.87 ; 62.53,6236.36 68.28,6236.36 74.03,6230.61 79.78,6236.36 85.53,6236.36 79.78,6242.11 85.53,6247.86 79.78,6247.86 74.03,6253.61 68.28,6247.86 62.53,6247.86 68.28,6242.11 62.53,6236.36 ; 62.53,6293.86 74.03,6282.36 85.53,6293.86 74.03,6305.36 62.53,6293.86 ; 62.53,6339.85 68.28,6339.85 74.03,6334.1 79.78,6339.85 85.53,6339.85 79.78,6345.6 85.53,6351.35 79.78,6351.35 74.03,6357.1 68.28,6351.35 62.53,6351.35 68.28,6345.6 62.53,6339.85 ; 62.53,6385.85 62.53,6391.6 68.28,6397.35 62.53,6403.09 62.53,6408.84 68.28,6408.84 74.03,6403.09 79.78,6408.84 85.53,6408.84 85.53,6403.09 79.78,6397.35 85.53,6391.6 85.53,6385.85 79.78,6385.85 74.03,6391.6 68.28,6385.85 62.53,6385.85 ; 62.53,6437.59 74.03,6443.34 85.53,6437.59 79.78,6449.09 85.53,6460.59 74.03,6454.84 62.53,6460.59 68.28,6449.09 62.53,6437.59 ; 67.13,6342.15 70.58,6342.15 74.03,6338.7 77.48,6342.15 80.93,6342.15 77.48,6345.6 80.93,6349.05 77.48,6349.05 74.03,6352.5 70.58,6349.05 67.13,6349.05 70.58,6345.6 67.13,6342.15
  lines w12: 39.86,6008.12 1384.26,6008.12 ; 39.86,6473.81 1384.26,6473.81 ; 180.41,5956.37 180.41,6525.56 ; 318.52,5956.37 318.52,6525.56 ; 583.3,5956.37 583.3,6525.56 ; 691.1,5956.37 691.1,6525.56 ; 847.16,5956.37 847.16,6525.56 ; 1148.64,5956.37 1148.64,6525.56 ; 39.86,5956.37 1384.26,5956.37 1384.26,6525.56 39.86,6525.56 39.86,5956.37
  text "Symbol" at 70.9,6489.33 h30
  text "Quantity" at 195.94,6489.33 h30
  text "Finished Hole Size" at 334.04,6489.33 h30
  text "Plated" at 598.82,6489.33 h30
  text "Hole Type" at 706.63,6489.33 h30
  text "Drill Layer Pair" at 862.68,6489.33 h30
  text "Hole Tolerance" at 1164.16,6489.33 h30
  text "6" at 195.94,6437.59 h25
  text "7.87mil (0.200mm)" at 334.04,6437.59 h25
  text "PTH" at 598.82,6437.59 h25
  text "Round" at 706.63,6437.59 h25
  text "Top Layer - Bottom Layer" at 862.68,6437.59 h25
  text "195" at 195.94,6385.85 h25
  text "8.00mil (0.203mm)" at 334.04,6385.85 h25
  text "PTH" at 598.82,6385.85 h25
  text "Round" at 706.63,6385.85 h25
  text "Top Layer - Bottom Layer" at 862.68,6385.85 h25
  text "6" at 195.94,6334.1 h25
  text "33.47mil (0.850mm)" at 334.04,6334.1 h25
  text "PTH" at 598.82,6334.1 h25
  text "Round" at 706.63,6334.1 h25
  text "Top Layer - Bottom Layer" at 862.68,6334.1 h25
  text "4" at 195.94,6282.36 h25
  text "40.00mil (1.016mm)" at 334.04,6282.36 h25
  text "PTH" at 598.82,6282.36 h25
  text "Round" at 706.63,6282.36 h25
  text "Top Layer - Bottom Layer" at 862.68,6282.36 h25
  text "8" at 195.94,6230.61 h25
  text "43.31mil (1.100mm)" at 334.04,6230.61 h25
  text "PTH" at 598.82,6230.61 h25
  text "Round" at 706.63,6230.61 h25
  text "Top Layer - Bottom Layer" at 862.68,6230.61 h25
  text "19" at 195.94,6178.87 h25
  text "45.28mil (1.150mm)" at 334.04,6178.87 h25
  text "PTH" at 598.82,6178.87 h25
  text "Round" at 706.63,6178.87 h25
  text "Top Layer - Bottom Layer" at 862.68,6178.87 h25
  text "8" at 195.94,6127.13 h25
  text "51.18mil (1.300mm)" at 334.04,6127.13 h25
  text "PTH" at 598.82,6127.13 h25
  text "Round" at 706.63,6127.13 h25
  text "Top Layer - Bottom Layer" at 862.68,6127.13 h25
  text "7" at 195.94,6075.38 h25
  text "63.00mil (1.600mm)" at 334.04,6075.38 h25
  text "PTH" at 598.82,6075.38 h25
  text "Round" at 706.63,6075.38 h25
  text "Top Layer - Bottom Layer" at 862.68,6075.38 h25
  text "3" at 195.94,6023.64 h25
  text "31.50mil (0.800mm)" at 334.04,6023.64 h25
  text "PTH" at 598.82,6023.64 h25
  text "Slot" at 706.63,6023.64 h25
  text "Top Layer - Bottom Layer" at 862.68,6023.64 h25
  text "256 Total" at 195.94,5971.89 h25
  text "Slot definitions :" at 70.9,5935.67 h25
  text "Routed Path Length" at 258.5,5935.67 h25
  text "= Calculated from tool start centre position to tool end centre position." at 483.15,5935.67 h25
  text "Hole Length" at 258.5,5914.98 h25
  text "= Routed Path Length + Tool Size = Slot length as defined in the PCB layout" at 399.99,5914.98 h25
  text ".Layer_Name" at 575,-2292.49 h25
Mechanical 17:
  text ".Layer_Name" at 575,-2292.49 h25
Mechanical 18:
  text ".Layer_Name" at 575,-2292.49 h25
Mechanical 19:
  text ".Layer_Name" at 575,-2292.49 h25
